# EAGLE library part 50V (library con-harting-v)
CONNECTOR
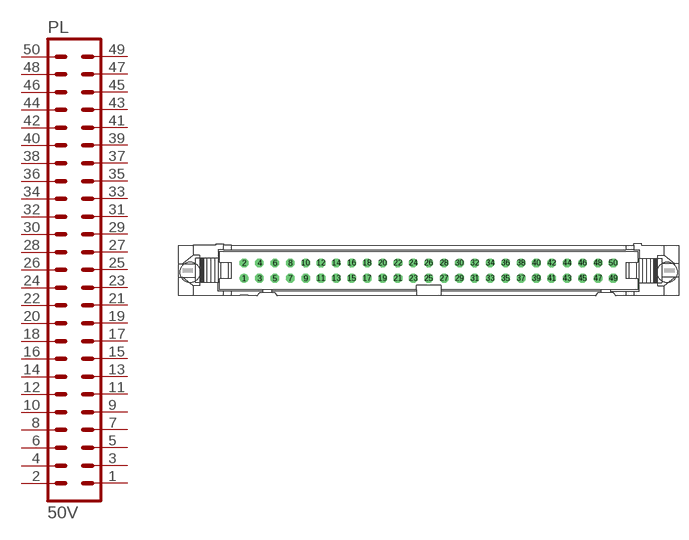
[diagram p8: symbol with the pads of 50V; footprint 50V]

Designator prefix PL

## 50V (OC_FARNELL: unknown; OC_NEWARK: unknown)  [50V]
1  1  pas
2  2  pas
3  3  pas
4  4  pas
5  5  pas
6  6  pas
7  7  pas
8  8  pas
9  9  pas
10  10  pas
11  11  pas
12  12  pas
13  13  pas
14  14  pas
15  15  pas
16  16  pas
17  17  pas
18  18  pas
19  19  pas
20  20  pas
21  21  pas
22  22  pas
23  23  pas
24  24  pas
25  25  pas
26  26  pas
27  27  pas
28  28  pas
29  29  pas
30  30  pas
31  31  pas
32  32  pas
33  33  pas
34  34  pas
35  35  pas
36  36  pas
37  37  pas
38  38  pas
39  39  pas
40  40  pas
41  41  pas
42  42  pas
43  43  pas
44  44  pas
45  45  pas
46  46  pas
47  47  pas
48  48  pas
49  49  pas
50  50  pas

## Footprint 50V (pad centres in mm)
CONNECTOR
drill 0.914 round: 1 -30.48,-1.27
drill 0.914 octagon: 2 -30.48,1.27; 3 -27.94,-1.27; 4 -27.94,1.27; 5 -25.4,-1.27; 6 -25.4,1.27; 7 -22.86,-1.27; 8 -22.86,1.27; 9 -20.32,-1.27; 10 -20.32,1.27; 11 -17.78,-1.27; 12 -17.78,1.27; 13 -15.24,-1.27; 14 -15.24,1.27; 15 -12.7,-1.27; 16 -12.7,1.27; 17 -10.16,-1.27; 18 -10.16,1.27; 19 -7.62,-1.27; 20 -7.62,1.27; 21 -5.08,-1.27; 22 -5.08,1.27; 23 -2.54,-1.27; 24 -2.54,1.27; 25 0,-1.27; 26 0,1.27; 27 2.54,-1.27; 28 2.54,1.27; 29 5.08,-1.27; 30 5.08,1.27; 31 7.62,-1.27; 32 7.62,1.27; 33 10.16,-1.27; 34 10.16,1.27; 35 12.7,-1.27; 36 12.7,1.27; 37 15.24,-1.27; 38 15.24,1.27; 39 17.78,-1.27; 40 17.78,1.27; 41 20.32,-1.27; 42 20.32,1.27; 43 22.86,-1.27; 44 22.86,1.27; 45 25.4,-1.27; 46 25.4,1.27; 47 27.94,-1.27; 48 27.94,1.27; 49 30.48,-1.27; 50 30.48,1.27
hole 3.302 at 39.37,-0.254
hole 3.302 at -39.37,-0.254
